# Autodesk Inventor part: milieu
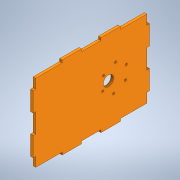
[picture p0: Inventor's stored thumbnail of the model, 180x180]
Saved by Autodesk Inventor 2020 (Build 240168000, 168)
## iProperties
Created: 2023-12
Part Number: milieu
Material: Générique
Document SubType Name: Modeling
Designer: bruno
Density: 1 g/cm^3
Appearance: Orange
Author: bruno
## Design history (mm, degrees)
sketch "Esquisse1"
  geometry: L1 (59.938, 165)-(82.812, 165); L2 (59.938, 162)-(59.938, 165); L3 (37.062, 162)-(59.938, 162); L4 (37.062, 165)-(37.062, 162); L5 (14.188, 165)-(37.062, 165); L6 (14.188, 162)-(14.188, 165); L7 (0, 162)-(14.188, 162); L8 (82.812, 165)-(82.812, 162); L9 (0, 182.812)-(0, 162); L10 (97, 318)-(0, 318); L11 (97, 297.188)-(97, 318); L12 (94, 297.188)-(97, 297.188); L13 (94, 274.312)-(94, 297.188); L14 (97, 274.312)-(94, 274.312); L15 (97, 251.438)-(97, 274.312); L16 (94, 251.438)-(97, 251.438); L17 (94, 228.563)-(94, 251.438); L18 (97, 228.563)-(94, 228.563); L19 (97, 205.688)-(97, 228.563); L20 (94, 205.688)-(97, 205.688); L21 (94, 182.812)-(94, 205.688); L22 (3, 205.688)-(3, 182.812); L23 (0, 205.688)-(3, 205.688); L24 (0, 228.563)-(0, 205.688); L25 (3, 228.563)-(0, 228.563); L26 (3, 182.812)-(0, 182.812); L27 (0, 318)-(0, 297.188); L28 (3, 251.438)-(3, 228.563); L29 (0, 251.438)-(3, 251.438); L30 (0, 274.312)-(0, 251.438); L31 (3, 274.312)-(0, 274.312); L32 (3, 297.188)-(3, 274.312); L33 (0, 297.188)-(3, 297.188); L34 (97, 182.812)-(94, 182.812); L35 (97, 162)-(97, 182.812); L36 (82.812, 162)-(97, 162); L37 (337, 82.938)-(337, 105.812); L38 (243, 60.063)-(240, 60.063); L39 (243, 82.938)-(243, 60.063); L40 (240, 82.938)-(243, 82.938); L41 (240, 105.812)-(240, 82.938); L42 (243, 105.812)-(240, 105.812); L43 (243, 137)-(243, 105.812); L44 (337, 105.812)-(334, 105.812); L45 (334, 105.812)-(334, 128.688); L46 (334, 128.688)-(334, 137); L47 (334, 137)-(322.812, 137); L48 (322.812, 137)-(322.812, 140); L49 (322.812, 140)-(299.938, 140); L50 (299.938, 140)-(299.938, 137); L51 (299.938, 137)-(277.062, 137); L52 (277.062, 137)-(277.062, 140); L53 (277.062, 140)-(254.188, 140); L54 (254.188, 140)-(254.188, 137); L55 (254.188, 137)-(243, 137); L56 (254.188, 6)-(254.188, 3); L57 (243, 6)-(254.188, 6); L58 (243, 14.313)-(243, 6); L59 (243, 37.188)-(243, 14.313); L60 (240, 37.188)-(243, 37.188); L61 (240, 60.063)-(240, 37.188); L62 (277.062, 3)-(277.062, 6); L63 (277.062, 6)-(299.938, 6); L64 (299.938, 6)-(299.938, 3)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; 39 further points
  constraints: 368 end point
extrude "Extrusion1" new body sketch "Esquisse1" distance "d0" = 3; taper "d1" = 0 deg
sketch "Esquisse2"
  geometry: L1 (54.979, 13.833)-(54.979, -11.467); L2 (-81.021, -11.467)-(-81.021, 13.833); L3 (51.979, 13.833)-(54.979, 13.833); L4 (54.979, 13.833)-(54.979, -11.467); L5 (54.979, -11.467)-(51.979, -11.467); L6 (31.979, 49.183)-(6.679, 49.183); L7 (6.679, 49.183)-(6.679, 46.183); L8 (31.979, 46.183)-(31.979, 49.183); L9 (-32.721, 49.183)-(-58.021, 49.183); L10 (-58.021, 49.183)-(-58.021, 46.183); L11 (-32.721, 46.183)-(-32.721, 49.183); L12 (31.979, -43.817)-(31.979, -46.817); L13 (31.979, -46.817)-(6.679, -46.817); L14 (6.679, -46.817)-(6.679, -43.817); L15 (-58.021, -43.817)-(-58.021, -46.817); L16 (-58.021, -46.817)-(-32.721, -46.817); L17 (-32.721, -46.817)-(-32.721, -43.817); L18 (-78.021, 13.833)-(-81.021, 13.833); L19 (-81.021, 13.833)-(-81.021, -11.467); L20 (-81.021, -11.467)-(-78.021, -11.467); L21 (51.979, -43.817)-(51.979, -11.467); L22 (51.979, 13.833)-(51.979, 46.183); L23 (-58.021, 49.183)-(-32.721, 49.183); L24 (6.679, 49.183)-(31.979, 49.183); L25 (31.979, -46.817)-(6.679, -46.817); L26 (-32.721, -46.817)-(-58.021, -46.817); L27 (31.979, -43.817)-(51.979, -43.817); L28 (51.979, 46.183)-(31.979, 46.183); L29 (6.679, 46.183)-(-32.721, 46.183); L30 (-58.021, 46.183)-(-78.021, 46.183); L31 (-78.021, -43.817)-(-58.021, -43.817); L32 (-32.721, -43.817)-(6.679, -43.817); L33 (-78.021, 46.183)-(-78.021, 13.833); L34 (-78.021, -11.467)-(-78.021, -43.817); L35 (-33.25, 375.8)-(-69.35, 375.8); L36 (-69.35, 239.2)-(-33.25, 239.2); L37 (-33.25, 375.8)-(-69.35, 375.8); L38 (-51.3, 375.8)-(-51.3, 239.2); L39 (-69.35, 239.2)-(-33.25, 239.2); L40 (-51.3, 289.14)-(-49.844, 289.14); L41 (-6, 277.062)-(-6, 299.938) reference; L42 (-6, 288.5)-(-65.63, 288.5); C1 r 6 at (-51.267, 288.5); C2 r 1.229 at (-58.231, 281.295); C3 r 1.229 at (-31.454, 279.35); C4 r 1.229 at (-43.158, 303.512); C5 r 1.229 at (-30.332, 294.81); C6 r 1.229 at (-45.404, 272.593); C7 r 1.229 at (-57.108, 296.755); 5 further points
  constraints: 82 end point, 24 parallel, 14 perpendicular, 7 centre point, 6 horizontal, 3 midpoint, 1 point on line, 2 other
  dimensions: "d2" = 25.3 distance between parallel lines of L7 L8; "d3" = 25.3 distance between parallel lines of L10 L11 (= d2); "d4" = 25.3 distance between parallel lines of L15 L17 (= d5); "d5" = 25.3 distance between parallel lines of L14 L12 (= d6); "d6" = 25.3 distance between parallel lines of L5 L3 (= d2); "d7" = 25.3 distance between parallel lines of L20 L18 (= d4); "d8" = 86.66 distance from line of L40.end L35
extrude "Extrusion2" cut sketch "Esquisse2" distance "d9" = 10; taper "d10" = 0 deg
node "Solide1"
